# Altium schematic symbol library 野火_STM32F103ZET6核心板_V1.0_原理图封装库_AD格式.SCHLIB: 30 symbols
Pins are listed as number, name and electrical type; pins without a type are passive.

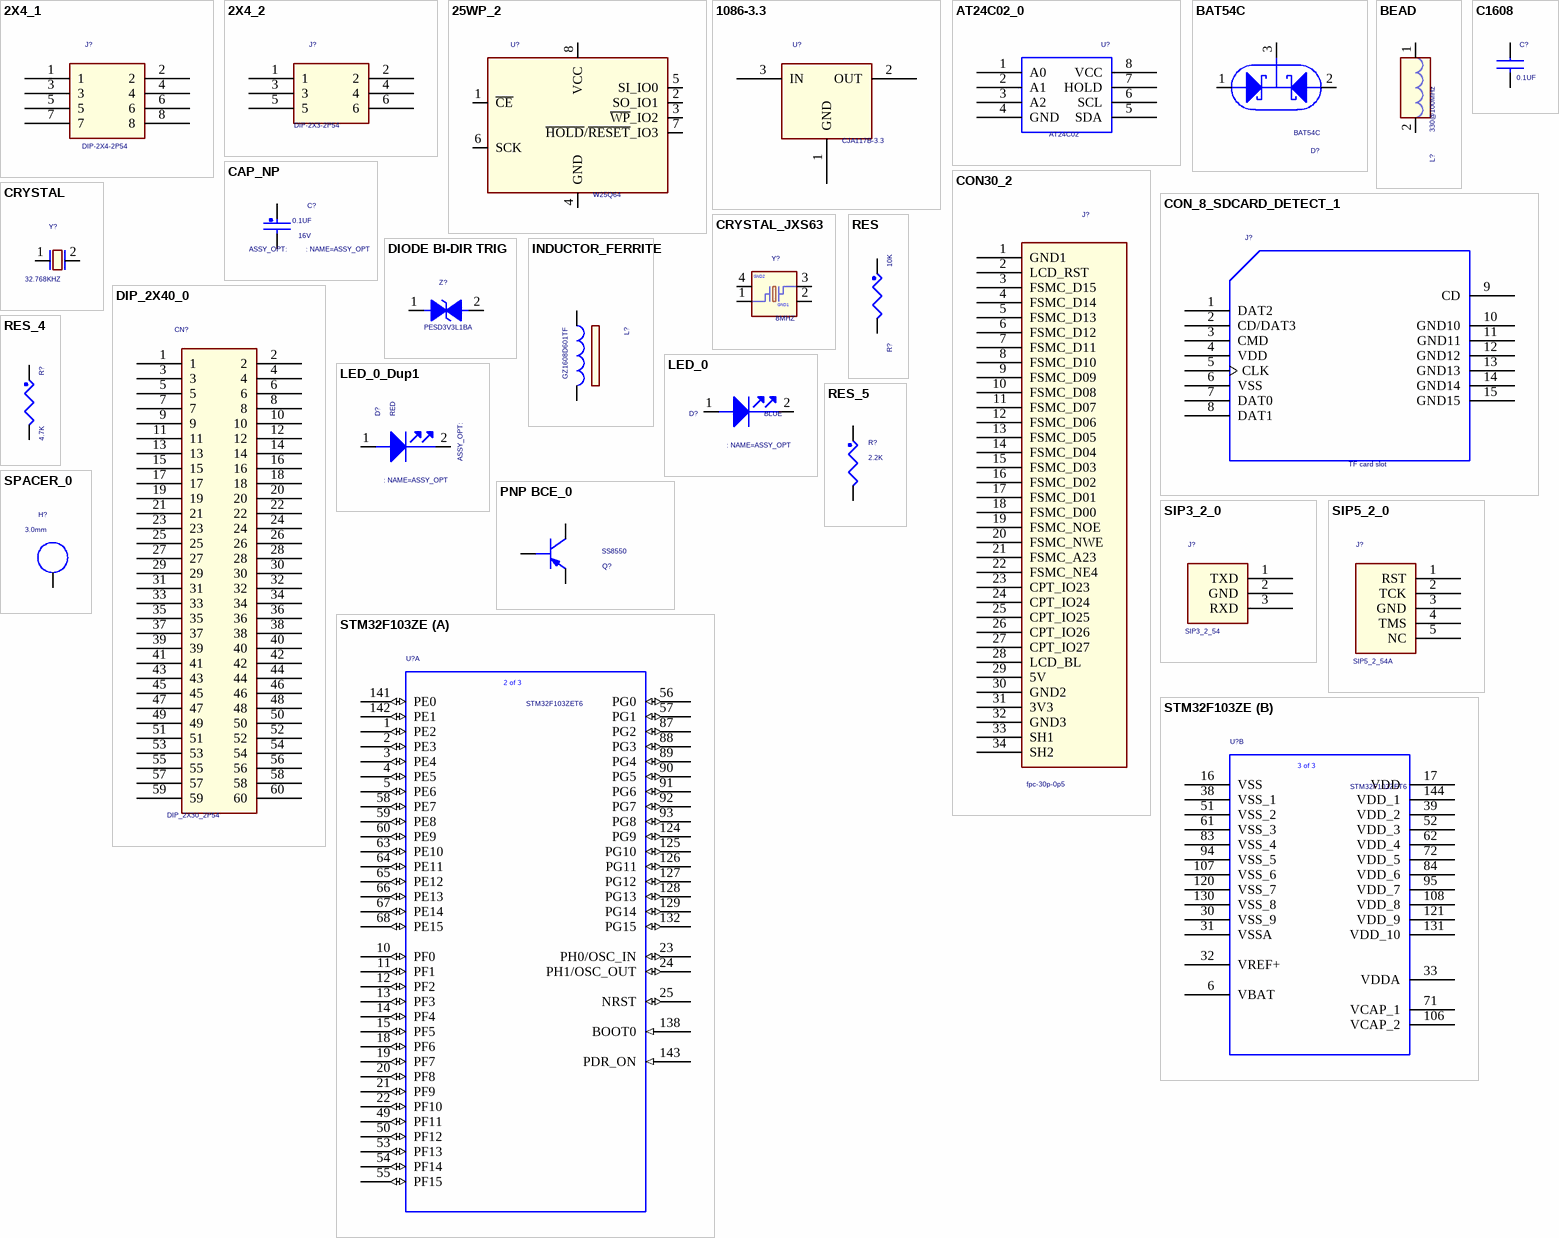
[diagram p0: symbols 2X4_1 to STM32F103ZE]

## 2X4_1
designator J?, comment DIP-2X4-2P54
footprint 2X4_2P54
footprint DIP-2X4-2P54
pins: 1, 2, 3, 4, 5, 6, 7, 8

## 2X4_2
designator J?, comment DIP-2X3-2P54
footprint 2X4_2P54
footprint DIP-2X3-2P54
pins: 1, 2, 3, 4, 5, 6

## 25WP_2
designator U?, comment W25Q64
IC MEM FLASH QPI 64Mb 1.65-1.95V SOIC8W; CAD_APPROVED: Yes; Temp_Range: -40C to +105C; MFG_PN01: IS25WP064A-JBLE; MFG_NAME01: ISSI; AGILE_PN: 334-77734
footprint SOIC8-208
pins: 1 ~{CE}, 2 SO_IO1, 3 ~{WP}_IO2, 4 GND (power), 5 SI_IO0, 6 SCK, 7 ~{HOLD}/~{RESET}_IO3, 8 VCC (power)

## 1086-3.3
designator U?, comment CJA117B-3.3
footprint TO252-2
footprint SOT89
pins: 1 GND, 2 OUT, 3 IN

## AT24C02_0
designator U?, comment AT24C02
OriginalSymbolOrigin: (-20000,30000)
footprint DIL08
footprint SOP8
pins: 1 A0, 2 A1, 3 A2, 4 GND, 5 SDA, 6 SCL, 7 HOLD, 8 VCC

## BAT54C
designator D?
footprint SOT23T02
footprint SOT23
pins: 1 ANODE, 2 NC, 3 CATHODE

## BEAD
designator L?, comment 330@100MHz
IND FER BEAD 330OHM@100MHZ 1.7A 0603; PART_TYPE: FERRITE\BEAD; CLASS: DISCRETE; AGILE_PN: 180-78156; Tolerance: 25%; MFG_NAME01: TDK; MFG_PN01: MPZ1608S331A; CAD_APPROVED: Yes
footprint L0603
pins: 1, 2

## C1608
designator C?, comment 0.1UF
footprint C1608
footprint C0402
pins: 1, 2

## CAP_NP
designator C?, comment 0.1UF  voltage rating: 16V
CAP CER 22UF 6.3V 20% X5R 0603; CLASS: DISCRETE; AGILE_PN: 150-78467; MFG_NAME01: Samsung; MFG_PN01: CL10A226MQ8NRNE; CAD_APPROVED: Yes; FPLIST: CC0603_OV,CC0603,0603_CC
footprint C0402
pins: 1, 2

## CON30_2
designator J?, comment fpc-30p-0p5
footprint fpc-32p-0p5
pins: 1 GND1, 2 LCD_RST, 3 FSMC_D15, 4 FSMC_D14, 5 FSMC_D13, 6 FSMC_D12, 7 FSMC_D11, 8 FSMC_D10, 9 FSMC_D09, 10 FSMC_D08, 11 FSMC_D07, 12 FSMC_D06, 13 FSMC_D05, 14 FSMC_D04, 15 FSMC_D03, 16 FSMC_D02, 17 FSMC_D01, 18 FSMC_D00, 19 FSMC_NOE, 20 FSMC_NWE, 21 FSMC_A23, 22 FSMC_NE4, 23 CPT_IO23, 24 CPT_IO24, 25 CPT_IO25, 26 CPT_IO26, 27 CPT_IO27, 28 LCD_BL, 29 5V, 30 GND2, 31 3V3, 32 GND3, 33 SH1, 34 SH2

## CON_8_SDCARD_DETECT_1
designator J?, comment TF card slot
CON 8 SKT SD/MMC PUSH-PUSH RA SMT 1.1MM SP 83H AU; CLASS: IO; AGILE_PN: 211-80105; MFG_NAME01: ANYTRONIC CORPORATION LIMITED; MFG_PN01: 95060030-14RRF; CAD_APPROVED: Yes
footprint TFCARD
pins: 1 DAT2, 2 CD/DAT3, 3 CMD, 4 VDD (power), 5 CLK, 6 VSS (power), 7 DAT0, 8 DAT1, 9 CD, 10 GND10, 11 GND11, 12 GND12, 13 GND13, 14 GND14, 15 GND15

## CRYSTAL
designator Y?, comment 32.768KHZ
XTAL 32.768KHZ 7PF 20PPM -- SMT; CLASS: IC; AGILE_PN: 230-78102; MFG_NAME01: EPSON ELECTRONICS; MFG_PN01: FC-135 32.7680KA-AG3; CAD_APPROVED: Yes
footprint 3215
pins: 1, 2

## CRYSTAL_JXS63
designator Y?, comment 8MHZ
XTAL 24MHZ -- 30PPM 3.2X2.5MM SMD; CLASS: IC; CAD_APPROVED: Yes; MFG_PN01: 7V24000002; MFG_NAME01: TXC CORP; AGILE_PN: 230-77452
footprint 3225
pins: 1, 2 GND1 (power), 3, 4 GND2 (power)

## DIODE BI-DIR TRIG
designator Z?, comment PESD3V3L1BA
Assembly: NC; ROOM: B-VGA_IN
footprint D0603/SMD
footprint SOD323
pins: 1, 2

## DIP_2X40_0
designator CN?, comment DIP_2X30_2P54
footprint DIP-2X302P54
pins: 1, 2, 3, 4, 5, 6, 7, 8, 9, 10, 11, 12, 13, 14, 15, 16, 17, 18, 19, 20, 21, 22, 23, 24, 25, 26, 27, 28, 29, 30, 31, 32, 33, 34, 35, 36, 37, 38, 39, 40, 41, 42, 43, 44, 45, 46, 47, 48, 49, 50, 51, 52, 53, 54, 55, 56, 57, 58, 59, 60

## INDUCTOR_FERRITE
designator L?, comment GZ1608D601TF
IND FER BEAD 120 OHM@100MHZ 0.5A 25% 0402; PART_TYPE: FERRITE\BEAD; CLASS: DISCRETE; FPLIST: IND_0402,0402_CC; CAD_APPROVED: Yes; MFG_PN01: BLM15AG121SN1D; MFG_NAME01: Murata; AGILE_PN: 180-77771
footprint L0603
pins: 1, 2

## LED_0
designator D?, comment BLUE
CLASS: IC
footprint LED0603
pins: 1 ANODE, 2 CATHODE

## LED_0_Dup1
designator D?, comment RED
LED GRN SGL 25MA 0603; CLASS: IC; AGILE_PN: 370-76549; MFG_NAME01: KINGBRIGHT; MFG_PN01: KPT-1608SGC; CAD_APPROVED: Yes
footprint LED0603
pins: 1 ANODE, 2 CATHODE

## PNP BCE_0
designator Q?, comment SS8550
footprint SOT23
pins: 1 B, 2 E, 3 C

## RES
designator R?, comment 10K
RES MF 1.0M 1/10W 5% 0402; CLASS: DISCRETE; AGILE_PN: 470-79978; MFG_NAME01: PANASONIC; MFG_PN01: ERJ-2GEJ105X; CAD_APPROVED: Yes; FPLIST: RC0402_25,RC0402_HD,0402_CC
footprint R0402
pins: 1, 2

## RES_4
designator R?, comment 4.7K
RES MF 4.7K 1/16W 5% 0402; CLASS: DISCRETE; FPLIST: RC0402_25,RC0402_HD,0402_CC; CAD_APPROVED: Yes; MFG_PN01: RK73B1ETTP472J; MFG_NAME01: KOA SPEER; AGILE_PN: 470-75626
footprint R0402
pins: 1, 2

## RES_5
designator R?, comment 2.2K
RES MF 10K 1/16W 5% 0402; CLASS: DISCRETE; FPLIST: RC0402_25,RC0402_HD,0402_CC; CAD_APPROVED: Yes; MFG_PN01: CRCW040210K0JNED; MFG_NAME01: VISHAY INTERTECHNOLOGY; AGILE_PN: 470-75557
footprint R0402
pins: 1, 2

## SIP3_2_0
designator J?, comment SIP3_2_54
footprint SIP3-2P54
pins: 1 TXD, 2 GND, 3 RXD

## SIP5_2_0
designator J?, comment SIP5_2_54A
footprint SIP5-2P54
pins: 1 RST, 2 TCK, 3 GND, 4 TMS, 5 NC

## SPACER_0
designator H?, comment 3.0mm
FASTENER, STANDOFF 4.5MMX3.53XM3.0X0.5 ROUND THR .635"L BRASS; CLASS: IC; CAD_APPROVED: Yes; ASSY_OPT: DNP; MFG_PN01: MSS251-R-1-A-16; MFG_NAME01: UNICORP; AGILE_PN: 280-76498
footprint t3-5p5
pins: 1 NC_1

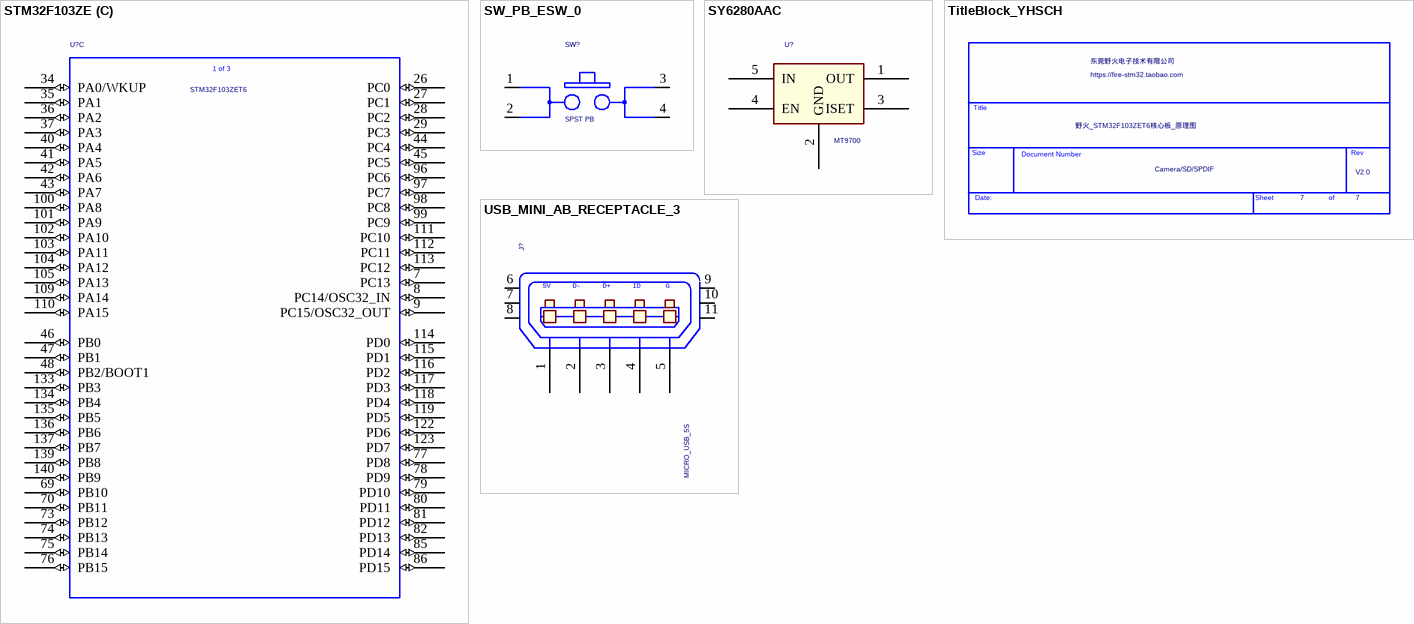
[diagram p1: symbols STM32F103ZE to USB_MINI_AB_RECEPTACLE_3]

## STM32F103ZE
designator U?, comment STM32F103ZET6
Manufacturer_Part_Number: stm32f4xxz1; OriginalSymbolOrigin: (30000,20000); Vendor: STMicroelectronics; Designator: 3
footprint LQFP144-20x20mm
footprint LQFP144-050-2020
part A pins: 1 PE2 (io), 2 PE3 (io), 3 PE4 (io), 4 PE5 (io), 5 PE6 (io), 10 PF0 (io), 11 PF1 (io), 12 PF2 (io), 13 PF3 (io), 14 PF4 (io), 15 PF5 (io), 18 PF6 (io), 19 PF7 (io), 20 PF8 (io), 21 PF9 (io), 22 PF10 (io), 23 PH0/OSC_IN (io), 24 PH1/OSC_OUT (io), 25 NRST (io), 49 PF11 (io), 50 PF12 (io), 53 PF13 (io), 54 PF14 (io), 55 PF15 (io), 56 PG0 (io), 57 PG1 (io), 58 PE7 (io), 59 PE8 (io), 60 PE9 (io), 63 PE10 (io), 64 PE11 (io), 65 PE12 (io), 66 PE13 (io), 67 PE14 (io), 68 PE15 (io), 87 PG2 (io), 88 PG3 (io), 89 PG4 (io), 90 PG5 (io), 91 PG6 (io), 92 PG7 (io), 93 PG8 (io), 124 PG9 (io), 125 PG10 (io), 126 PG11 (io), 127 PG12 (io), 128 PG13 (io), 129 PG14 (io), 132 PG15 (io), 138 BOOT0 (in), 141 PE0 (io), 142 PE1 (io), 143 PDR_ON (in)
part B pins: 6 VBAT (power), 16 VSS (power), 17 VDD (power), 30 VSS_9 (power), 31 VSSA (power), 32 VREF+ (power), 33 VDDA (power), 38 VSS_1 (power), 39 VDD_2 (power), 51 VSS_2 (power), 52 VDD_3 (power), 61 VSS_3 (power), 62 VDD_4 (power), 71 VCAP_1 (power), 72 VDD_5 (power), 83 VSS_4 (power), 84 VDD_6 (power), 94 VSS_5 (power), 95 VDD_7 (power), 106 VCAP_2 (power), 107 VSS_6 (power), 108 VDD_8 (power), 120 VSS_7 (power), 121 VDD_9 (power), 130 VSS_8 (power), 131 VDD_10 (power), 144 VDD_1 (power)
part C pins: 7 PC13 (io), 8 PC14/OSC32_IN (io), 9 PC15/OSC32_OUT (io), 26 PC0 (io), 27 PC1 (io), 28 PC2 (io), 29 PC3 (io), 34 PA0/WKUP (io), 35 PA1 (io), 36 PA2 (io), 37 PA3 (io), 40 PA4 (io), 41 PA5 (io), 42 PA6 (io), 43 PA7 (io), 44 PC4 (io), 45 PC5 (io), 46 PB0 (io), 47 PB1 (io), 48 PB2/BOOT1 (io), 69 PB10 (io), 70 PB11 (io), 73 PB12 (io), 74 PB13 (io), 75 PB14 (io), 76 PB15 (io), 77 PD8 (io), 78 PD9 (io), 79 PD10 (io), 80 PD11 (io), 81 PD12 (io), 82 PD13 (io), 85 PD14 (io), 86 PD15 (io), 96 PC6 (io), 97 PC7 (io), 98 PC8 (io), 99 PC9 (io), 100 PA8 (io), 101 PA9 (io), 102 PA10 (io), 103 PA11 (io), 104 PA12 (io), 105 PA13 (io), 109 PA14 (io), 110 PA15 (io), 111 PC10 (io), 112 PC11 (io), 113 PC12 (io), 114 PD0 (io), 115 PD1 (io), 116 PD2 (io), 117 PD3 (io), 118 PD4 (io), 119 PD5 (io), 122 PD6 (io), 123 PD7 (io), 133 PB3 (io), 134 PB4 (io), 135 PB5 (io), 136 PB6 (io), 137 PB7 (io), 139 PB8 (io), 140 PB9 (io)

## SW_PB_ESW_0
designator SW?, comment SPST PB
SW SPST MOM NO PB TACT 50mA 50V SMT; CLASS: IC; AGILE_PN: 510-77562; MFG_NAME01: E SWITCH; MFG_PN01: TL3301AF260QG/TR; CAD_APPROVED: Yes
footprint SW4_3X3P5
pins: 1 A1, 2 A2, 3 B1, 4 B2

## SY6280AAC
designator U?, comment MT9700
footprint SOT23-5
pins: 1 OUT, 2 GND, 3 ISET, 4 EN, 5 IN

## TitleBlock_YHSCH
designator *?  Page Count: 7  OrgName: 东莞野火电子技术有限公司  Title: 野火_STM32F103ZET6核心板_原理图  RevCode: V2.0  Doc: Camera/SD/SPDIF  (hidden comment: TitleBlock_YHSCH)  (graphical)
Cage Code: 1

## USB_MINI_AB_RECEPTACLE_3
designator J?, comment MICRO_USB_5S
CON 5 USB MICRO_AB RA SKT SMT 0.65MM SP 110H AU; CLASS: IO; AGILE_PN: 211-80104; MFG_NAME01: ANYTRONIC CORPORATION LIMITED; MFG_PN01: 23970101#LCP-58LF; Temp_Range: -55&#8451; to 105&#8451;; CAD_APPROVED: Yes
footprint MICRO_USB_5S
pins: 1 P1, 2 P2, 3 P3, 4 P4, 5 P5, 6 SHLD1, 7 SHLD2, 8 SHLD3, 9 SHLD4, 10 SHLD5, 11 SHLD6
